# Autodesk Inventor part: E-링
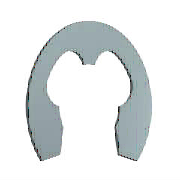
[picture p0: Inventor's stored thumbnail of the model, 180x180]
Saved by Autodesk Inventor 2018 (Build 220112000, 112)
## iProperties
IsCustomPart: 1
Created: 2012-02
Part Number: E-링
Material: 강철, 연강
Description: 일반용 테이퍼 및 줄어든 횡단면 리테이닝 링 - E-링 외부 시리즈 3CM1 리테이닝 링
Document SubType Name: Modeling
Standard: ANSI B27.7
Designer: mduedu
Standard Revision: 1999
Standards Organization: ANSI
Language: ko-KR
Size Designation: 6
Categories: <MemberInstance><Categories><Category DisplayName="샤프트 부품" InternalName="7f7aeb1f-a693-4053-b835-cee3144e0d98" Mnemonic="SHFT"><Category DisplayName="써클립" Inter
Density: 1 g/cm^3
Appearance: 파란색 - 벽 페인트 - 광택
Author: mduedu
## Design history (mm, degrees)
sketch "스케치1"
  geometry: L1 (-0.485, 0.024)-(0, 0.024) reference; L2 (-3.206, 0)-(3.486, 0) reference; L3 (-2.223, -3.946)-(2.223, -3.946); L4 (0, 1.949)-(0, -3.479) reference; L5 (-2.91, -2.006)-(-2.435, -2.006); L6 (-0.485, -0.066)-(-0.485, 0.405); L7 (0, 2.574)-(2.53, 2.574); L8 (-2.223, -3.946)-(-3.022, -6.291); L9 (0, -0.551)-(-1.278, -0.551); L10 (2.223, -3.946)-(3.022, -6.291); L11 (2.91, -2.006)-(2.435, -2.006); L12 (0.485, -0.066)-(0.485, 0.405); C1 r 3 at (0, -2.976); A1 r 2.425 centre (0, -2.976) between (-2.297, -2.199) and (-2.223, -3.946); A2 r 0.485 centre (0, -0.066) between (-0.485, -0.066) and (0.485, -0.066); A3 r 5.55 centre (0, -2.976) between (4.27, -6.521) and (-4.27, -6.521); A4 r 3.88 centre (0, -2.976) between (-0.97, 0.78) and (-3.424, -1.15); A5 r 0.388 centre (-0.873, 0.405) between (-0.485, 0.405) and (-0.97, 0.78); A6 r 0.582 centre (-2.91, -1.424) between (-3.424, -1.15) and (-2.91, -2.006); A7 r 0.145 centre (-2.435, -2.152) between (-2.297, -2.199) and (-2.435, -2.006); A8 r 0.727 centre (-3.711, -6.057) between (-4.27, -6.521) and (-3.022, -6.291); A9 r 0.727 centre (3.711, -6.057) between (3.022, -6.291) and (4.27, -6.521); A10 r 2.425 centre (0, -2.976) between (2.223, -3.946) and (2.297, -2.199); A11 r 0.145 centre (2.435, -2.152) between (2.435, -2.006) and (2.297, -2.199); A12 r 0.582 centre (2.91, -1.424) between (2.91, -2.006) and (3.424, -1.15); A13 r 3.88 centre (0, -2.976) between (3.424, -1.15) and (0.97, 0.78); A14 r 0.388 centre (0.873, 0.405) between (0.97, 0.78) and (0.485, 0.405); 1 further point
  constraints: 30 point on circle, 20 end point, 15 centre point, 13 symmetric about line, 12 tangent, 8 point on line, 4 parallel, 2 coincident, 2 horizontal, 1 concentric, 1 perpendicular, 1 vertical alignment, 9 other
  dimensions: "d0" = 6 diameter of C1 (= WD); "d3" = 0.97 distance from line of A1.centre L3 (= 0.2 x ND); "d4" = 0.485 radius of A2 (= 0.1 x ND); "d5" = 11.1 diameter of A3 (= SD2); "d8" = 3.88 radius of A4 (= 0.8 x ND); "d9" = 0.97 distance from line of A1.centre L5 (= 0.2 x ND); "d10" = 0.388 radius of A5 (= 0.08 x ND); "d11" = 0.582 radius of A6 (= 0.12 x ND); "d12" = 0.1455 radius of A7 (= 0.03 x ND); "d13" = 0.7275 radius of A8 (= 0.15 x ND); "d14" = 2.425 distance from line of A1.centre L9 (= 0.5 x ND); "d15" = 2.425 radius of A1 (= 0.5 x ND)
extrude "본체" new body sketch "스케치1" distance "d16" = 0.6 (= SD); taper "d17" = 0 deg
workaxis "Work Axis1"
workaxis "Work Axis2"
workplane "Work Plane1"
body "Solid1"
other parameters: "ND" = 4.85 [user parameter; used in 14 equation terms], "SD" = 0.6 [user parameter; used in 1 equation term], "WD" = 6 (= WDMIN) [user parameter; used in 1 equation term], "d1" = 7.76 (= 1.6 x ND), "d2" = 4.85 (= ND), "SD2" = 11.1 [user parameter; used in 1 equation term], "d6" = 4.85 (= ND), "d7" = 0.7275 (= 0.15 x ND), "d18" = 0, "d19" = 0, "d27" = 0, "d28" = 0, "WDMIN" = 6 [user parameter; used in 1 equation term], "SNB" = 0.7 [user parameter], "WDMAX" = 7 [user parameter], "BUBRMI" = 1.2 [user parameter]
